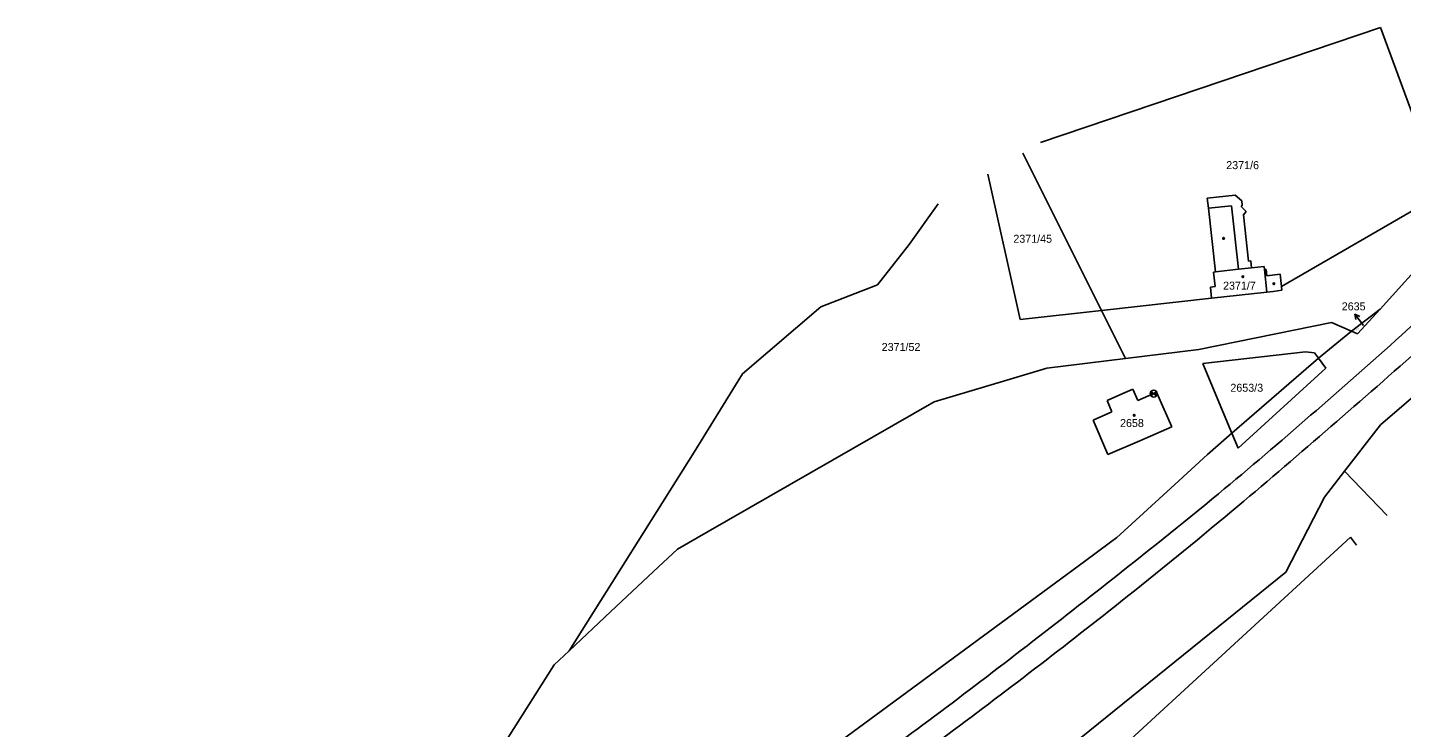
# Model space of a CAD drawing. Extents: x -825057 to -819383, y -1071633 to -1067888.
# Drawn here: x -820228.7 to -819936.8, y -1069432.8 to -1069284 of the extents above; entities that cross this region are included whole.
import ezdxf

# ---------------------------------------------------------------- set-up
doc = ezdxf.new("R2010")
doc.units = 0
for name, color, linetype in [('Vrstva 1', 7, 'Continuous'), ('Vrstva 10', 7, 'Continuous'), ('Vrstva 16', 7, 'Continuous'), ('Vrstva 18', 7, 'Continuous'), ('Vrstva 19', 7, 'Continuous'), ('Vrstva 24', 7, 'Continuous'), ('Vrstva 25', 7, 'Continuous'), ('Vrstva 4', 7, 'Continuous')]:
    doc.layers.add(name, color=color, linetype=linetype)

msp = doc.modelspace()

# ---------------------------------------------------------------- linework, layer by layer
at = {"layer": 'Vrstva 1'}
for p, q in [((-819941.28, -1069284.04), (-820013.54, -1069308.52)), ((-819928.32, -1069319.38), (-819941.28, -1069284.04)), ((-819941.4, -1069343.93), (-819899.08, -1069296.95)), ((-820017.26, -1069310.75), (-820000.54, -1069344.18)), ((-820024.73, -1069315.22), (-820017.81, -1069346.08)), ((-819978.09, -1069320.32), (-819972.13, -1069319.67)), ((-819972.13, -1069319.67), (-819970.75, -1069320.87)), ((-819962.32, -1069339.11), (-819928.32, -1069319.38)), ((-820041.44, -1069330.2), (-820035.28, -1069321.54)), ((-819977.86, -1069322.46), (-819978.09, -1069320.32)), ((-819976.37, -1069335.98), (-819977.86, -1069322.46)), ((-819970.65, -1069321.8), (-819970.92, -1069322.1)), ((-819970.92, -1069322.1), (-819969.8, -1069323.13)), ((-819970.75, -1069320.87), (-819970.65, -1069321.8)), ((-819969.8, -1069323.13), (-819970.42, -1069323.88)), ((-819970.42, -1069323.88), (-819969.34, -1069333.69)), ((-820048.1, -1069338.77), (-820041.44, -1069330.2)), ((-819969.34, -1069333.69), (-819968.84, -1069333.64)), ((-819968.84, -1069333.64), (-819968.67, -1069335.13)), ((-819976.76, -1069336.02), (-819976.37, -1069335.98)), ((-819976.43, -1069339.1), (-819976.76, -1069336.02)), ((-819968.67, -1069335.13), (-819966.03, -1069334.84)), ((-819966.03, -1069334.84), (-819965.96, -1069335.49)), ((-819965.96, -1069335.49), (-819965.56, -1069335.45)), ((-819965.56, -1069335.45), (-819965.41, -1069336.81)), ((-819965.41, -1069336.81), (-819962.61, -1069336.5)), ((-819962.61, -1069336.5), (-819962.32, -1069339.11)), ((-820060.16, -1069343.4), (-820048.1, -1069338.77)), ((-819977.42, -1069339.21), (-819976.43, -1069339.1)), ((-819977.16, -1069341.6), (-819977.42, -1069339.21)), ((-819965.43, -1069340.31), (-819977.16, -1069341.6)), ((-819965.43, -1069340.31), (-819964.11, -1069340.16)), ((-819962.23, -1069339.88), (-819964.11, -1069340.16)), ((-819962.32, -1069339.11), (-819962.23, -1069339.88)), ((-820076.82, -1069357.66), (-820060.16, -1069343.4)), ((-820000.54, -1069344.18), (-819977.16, -1069341.6)), ((-820017.81, -1069346.08), (-820000.54, -1069344.18)), ((-820000.54, -1069344.18), (-819995.44, -1069354.38)), ((-819941.4, -1069343.93), (-819947.47, -1069348.61)), ((-819946.15, -1069349.19), (-819941.4, -1069343.93)), ((-819979.86, -1069352.46), (-819951.73, -1069346.72)), ((-819951.73, -1069346.72), (-819947.47, -1069348.61)), ((-819947.47, -1069348.61), (-819946.15, -1069349.19)), ((-820012.13, -1069356.43), (-819995.44, -1069354.38)), ((-819995.44, -1069354.38), (-819979.86, -1069352.46)), ((-819979.02, -1069355.47), (-819957.23, -1069352.96)), ((-819957.23, -1069352.96), (-819955.32, -1069353.17)), ((-819955.32, -1069353.17), (-819954.47, -1069354.31)), ((-819954.47, -1069354.31), (-819952.89, -1069356.44)), ((-819941.27, -1069368.47), (-819923.96, -1069353.57)), ((-820087.09, -1069374.33), (-820076.82, -1069357.66)), ((-820020.63, -1069358.98), (-820012.13, -1069356.43)), ((-819978.37, -1069357.04), (-819979.02, -1069355.47)), ((-819972.86, -1069370.28), (-819978.37, -1069357.04)), ((-819952.89, -1069356.44), (-819971.54, -1069373.46)), ((-820036.1, -1069363.61), (-820020.63, -1069358.98)), ((-820084.08, -1069391.18), (-820036.1, -1069363.61)), ((-819999.38, -1069363.33), (-819996.64, -1069362.14)), ((-819998.33, -1069365.74), (-819999.38, -1069363.33)), ((-819996.64, -1069362.14), (-819993.91, -1069360.94)), ((-819993.91, -1069360.94), (-819992.85, -1069363.34)), ((-819992.85, -1069363.34), (-819989.46, -1069361.86)), ((-819989.46, -1069361.86), (-819988.85, -1069361.59)), ((-819988.85, -1069361.59), (-819985.65, -1069368.9)), ((-820002.34, -1069367.5), (-819998.33, -1069365.74)), ((-819999.19, -1069374.84), (-820002.34, -1069367.5)), ((-819985.65, -1069368.9), (-819992.42, -1069371.87)), ((-819948.91, -1069378.32), (-819941.27, -1069368.47)), ((-819992.42, -1069371.87), (-819999.19, -1069374.84)), ((-819971.54, -1069373.46), (-819972.86, -1069370.28)), ((-820113.65, -1069416.5), (-820087.09, -1069374.33)), ((-819953.2, -1069383.85), (-819948.91, -1069378.32)), ((-819939.89, -1069387.79), (-819948.91, -1069378.32)), ((-819961.4, -1069399.82), (-819953.2, -1069383.85)), ((-820090.62, -1069394.93), (-820084.08, -1069391.18)), ((-820006, -1069446.03), (-819947.67, -1069392.35)), ((-819947.67, -1069392.35), (-819946.41, -1069394.08)), ((-820095.68, -1069399.68), (-820090.62, -1069394.93)), ((-820104.79, -1069408.21), (-820095.68, -1069399.68)), ((-820013.16, -1069441.63), (-819961.4, -1069399.82)), ((-820113.65, -1069416.5), (-820104.79, -1069408.21)), ((-820116.82, -1069419.54), (-820113.65, -1069416.5)), ((-820131.78, -1069443.08), (-820116.82, -1069419.54))]:
    msp.add_line(p, q, dxfattribs=at)
at = {"layer": 'Vrstva 10'}
msp.add_line((-819896.02, -1069311.23), (-819936.83, -1069349.47), dxfattribs=at)
for points in [[(-819936.83, -1069349.47), (-819975.71, -1069383.16), (-819999.35, -1069402.16), (-820038.47, -1069432.26), (-820078.04, -1069460.09), (-820109.89, -1069479.65), (-820134.7, -1069493.27), (-820163.02, -1069506.83), (-820195.64, -1069520.53), (-820237.28, -1069534.88), (-820272.75, -1069545.33)], [(-820271.07, -1069550.51), (-820235.31, -1069539.9), (-820193.69, -1069525.37), (-820161.56, -1069511.74), (-820132.38, -1069497.54), (-820107.7, -1069483.92), (-820075.84, -1069464.22), (-820035.7, -1069436.13), (-819996.53, -1069406.13), (-819972.84, -1069386.82), (-819933.47, -1069352.83)]]:
    msp.add_spline(points, degree=3, dxfattribs=at)
at = {"layer": 'Vrstva 16'}
msp.add_line((-819944.89, -1069347.37), (-819946.722, -1069344.994), dxfattribs=at)
msp.add_lwpolyline([(-819946.507, -1069346.091), (-819946.722, -1069344.994), (-819945.715, -1069345.481)], dxfattribs=at)
at = {"layer": 'Vrstva 24'}
for p, q in [((-819990.21, -1069361.86), (-819988.71, -1069361.86)), ((-819990.184, -1069361.666), (-819988.736, -1069362.054)), ((-819990.184, -1069362.054), (-819988.736, -1069361.666)), ((-819990.109, -1069361.485), (-819988.811, -1069362.235)), ((-819990.109, -1069362.235), (-819988.811, -1069361.485)), ((-819989.99, -1069362.39), (-819988.93, -1069361.33)), ((-819989.99, -1069361.33), (-819988.93, -1069362.39))]:
    msp.add_line(p, q, dxfattribs=at)
msp.add_circle((-819989.46, -1069361.86), 0.75, dxfattribs=at)
at = {"layer": 'Vrstva 25'}
for centre in [(-819974.63, -1069328.88), (-819970.53, -1069337.02), (-819963.94, -1069338.51), (-819993.61, -1069366.47)]:
    msp.add_circle(centre, 0.175, dxfattribs=at)
at = {"layer": 'Vrstva 4'}
for p, q in [((-819977.86, -1069322.46), (-819972.95, -1069321.92)), ((-819972.95, -1069321.92), (-819971.46, -1069335.44)), ((-819976.37, -1069335.98), (-819971.46, -1069335.44)), ((-819971.46, -1069335.44), (-819968.67, -1069335.13)), ((-819965.96, -1069335.49), (-819965.43, -1069340.31)), ((-819954.47, -1069354.31), (-819947.47, -1069348.61)), ((-819972.86, -1069370.28), (-819954.47, -1069354.31)), ((-819978.05, -1069374.79), (-819972.86, -1069370.28)), ((-819984.97, -1069381.15), (-819978.05, -1069374.79)), ((-819996.61, -1069391.83), (-819984.97, -1069381.15)), ((-819998.62, -1069393.44), (-819997.29, -1069392.46)), ((-819997.29, -1069392.46), (-819996.61, -1069391.83)), ((-820004.18, -1069397.53), (-819998.62, -1069393.44)), ((-820076.53, -1069450.8), (-820004.18, -1069397.53))]:
    msp.add_line(p, q, dxfattribs=at)

# ---------------------------------------------------------------- texts
at = {"layer": 'Vrstva 16'}
msp.add_text('2635', height=1.7, dxfattribs=at).set_placement((-819949.526, -1069344.17))
at = {"layer": 'Vrstva 18'}
for s, p in [('2371/6', (-819974.056, -1069314.15)), ('2371/45', (-820019.276, -1069329.8)), ('2371/52', (-820047.241, -1069352.8)), ('2653/3', (-819973.177, -1069361.47))]:
    msp.add_text(s, height=1.7, dxfattribs=at).set_placement(p)
msp.add_text('2635', height=0.2, rotation=38.7, dxfattribs=at).set_placement((-819946.323, -1069348.406))
at = {"layer": 'Vrstva 19'}
for s, p in [('2371/7', (-819974.741, -1069339.77)), ('2658', (-819996.616, -1069368.97))]:
    msp.add_text(s, height=1.7, dxfattribs=at).set_placement(p)

doc.saveas('drawing.dxf')
